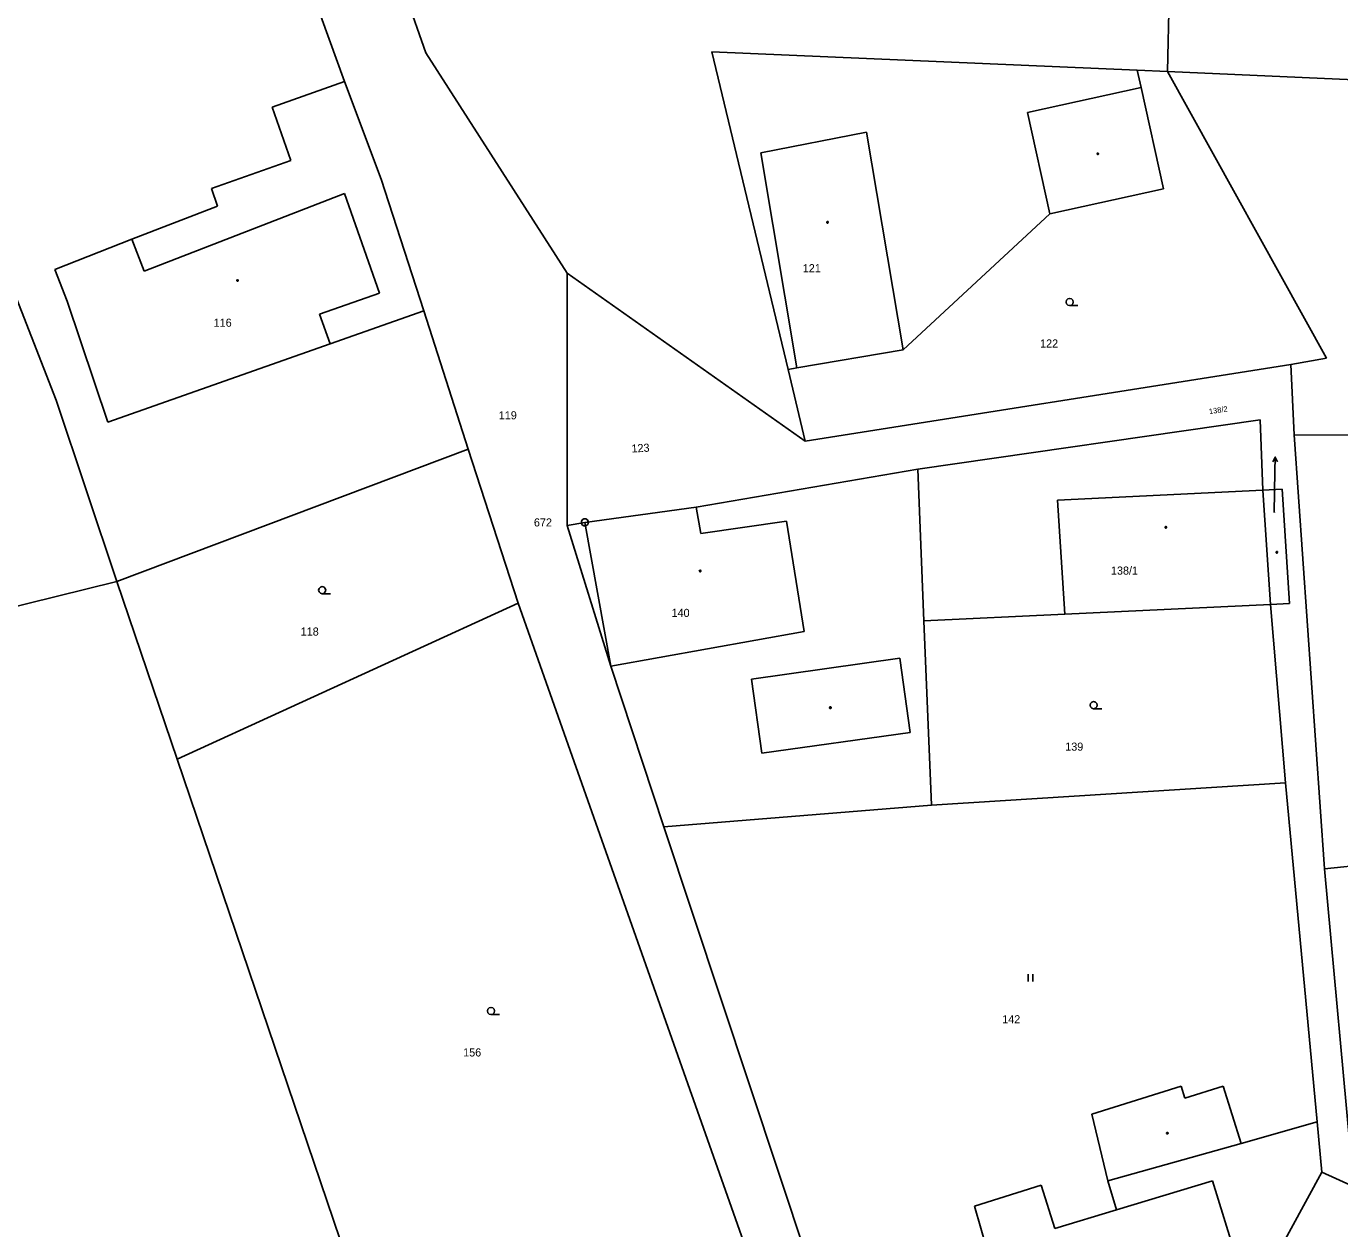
# Model space of a CAD drawing. Extents: x -871430 to -870620, y -1010094 to -1009649.
# Drawn here: x -870823.3 to -870754.3, y -1009884.4 to -1009821.3 of the extents above; entities that cross this region are included whole.
import ezdxf

# ---------------------------------------------------------------- set-up
doc = ezdxf.new("R2010")
doc.units = 0
for name, color, linetype in [('Vrstva 1', 7, 'Continuous'), ('Vrstva 2', 7, 'Continuous'), ('Vrstva 3', 7, 'Continuous'), ('Vrstva 4', 7, 'Continuous'), ('Vrstva 5', 7, 'Continuous'), ('Vrstva 7', 7, 'Continuous'), ('Vrstva 8', 7, 'Continuous')]:
    doc.layers.add(name, color=color, linetype=linetype)

msp = doc.modelspace()

# ---------------------------------------------------------------- linework, layer by layer
at = {"layer": 'Vrstva 1'}
for p, q in [((-870762.97, -1009806.25), (-870763.36, -1009823.67)), ((-870806.27, -1009811.26), (-870802.3, -1009822.69)), ((-870806.57, -1009824.19), (-870810.92, -1009812.17)), ((-870821.71, -1009840.91), (-870830.96, -1009817.26)), ((-870802.3, -1009822.69), (-870794.88, -1009834.25)), ((-870764.95, -1009823.6), (-870787.29, -1009822.63)), ((-870787.29, -1009822.63), (-870783.28, -1009839.3)), ((-870763.36, -1009823.67), (-870764.95, -1009823.6)), ((-870764.95, -1009823.6), (-870764.75, -1009824.51)), ((-870755.01, -1009838.71), (-870763.36, -1009823.67)), ((-870744.58, -1009824.51), (-870763.36, -1009823.67)), ((-870810.37, -1009825.53), (-870806.57, -1009824.19)), ((-870804.65, -1009829.31), (-870806.57, -1009824.19)), ((-870764.75, -1009824.51), (-870763.58, -1009829.82)), ((-870810.37, -1009825.53), (-870809.38, -1009828.34)), ((-870813.56, -1009829.81), (-870809.38, -1009828.34)), ((-870802.41, -1009836.23), (-870804.65, -1009829.31)), ((-870813.56, -1009829.81), (-870813.24, -1009830.73)), ((-870769.54, -1009831.14), (-870763.58, -1009829.82)), ((-870813.24, -1009830.73), (-870817.74, -1009832.47)), ((-870769.54, -1009831.14), (-870777.24, -1009838.28)), ((-870817.74, -1009832.47), (-870821.78, -1009834.05)), ((-870821.78, -1009834.05), (-870821.13, -1009835.72)), ((-870794.88, -1009834.25), (-870794.88, -1009847.5)), ((-870794.88, -1009834.25), (-870782.38, -1009843.06)), ((-870821.13, -1009835.72), (-870818.99, -1009842.07)), ((-870807.33, -1009837.96), (-870802.41, -1009836.23)), ((-870800.07, -1009843.48), (-870802.41, -1009836.23)), ((-870818.99, -1009842.07), (-870807.33, -1009837.96)), ((-870782.82, -1009839.22), (-870777.24, -1009838.28)), ((-870756.88, -1009839.04), (-870755.01, -1009838.71)), ((-870783.28, -1009839.3), (-870782.82, -1009839.22)), ((-870783.28, -1009839.3), (-870782.38, -1009843.06)), ((-870782.38, -1009843.06), (-870756.88, -1009839.04)), ((-870756.88, -1009839.04), (-870756.72, -1009842.74)), ((-870818.53, -1009850.43), (-870821.71, -1009840.91)), ((-870776.47, -1009844.53), (-870758.5, -1009841.94)), ((-870758.5, -1009841.94), (-870758.35, -1009845.64)), ((-870756.72, -1009842.74), (-870755.12, -1009865.52)), ((-870746.99, -1009842.77), (-870756.72, -1009842.74)), ((-870818.53, -1009850.43), (-870800.07, -1009843.48)), ((-870800.07, -1009843.48), (-870797.46, -1009851.56)), ((-870788.1, -1009846.53), (-870776.47, -1009844.53)), ((-870776.47, -1009844.53), (-870776.15, -1009852.5)), ((-870757.35, -1009845.59), (-870758.35, -1009845.64)), ((-870758.35, -1009845.64), (-870757.96, -1009851.63)), ((-870757.35, -1009845.59), (-870756.96, -1009851.58)), ((-870793.95, -1009847.33), (-870788.1, -1009846.53)), ((-870794.88, -1009847.5), (-870793.95, -1009847.33)), ((-870794.88, -1009847.5), (-870792.59, -1009854.88)), ((-870838.76, -1009855.45), (-870818.53, -1009850.43)), ((-870815.36, -1009859.75), (-870818.53, -1009850.43)), ((-870797.46, -1009851.56), (-870815.36, -1009859.75)), ((-870784.39, -1009888.53), (-870797.46, -1009851.56)), ((-870757.96, -1009851.63), (-870768.75, -1009852.15)), ((-870756.96, -1009851.58), (-870757.96, -1009851.63)), ((-870757.96, -1009851.63), (-870757.17, -1009861)), ((-870768.75, -1009852.15), (-870776.15, -1009852.5)), ((-870776.15, -1009852.5), (-870775.76, -1009862.17)), ((-870792.59, -1009854.88), (-870789.8, -1009863.3)), ((-870803.69, -1009894.13), (-870815.36, -1009859.75)), ((-870775.76, -1009862.17), (-870757.17, -1009861)), ((-870757.17, -1009861), (-870755.51, -1009878.79)), ((-870775.76, -1009862.17), (-870789.8, -1009863.3)), ((-870789.8, -1009863.3), (-870779.56, -1009894.18)), ((-870738.92, -1009863.81), (-870755.12, -1009865.52)), ((-870755.12, -1009865.52), (-870753.63, -1009881.72)), ((-870762.65, -1009876.91), (-870767.34, -1009878.38)), ((-870762.65, -1009876.91), (-870762.45, -1009877.54)), ((-870762.45, -1009877.54), (-870760.44, -1009876.91)), ((-870759.5, -1009879.92), (-870760.44, -1009876.91)), ((-870766.5, -1009881.89), (-870767.34, -1009878.38)), ((-870755.51, -1009878.79), (-870759.5, -1009879.92)), ((-870755.51, -1009878.79), (-870755.26, -1009881.44)), ((-870759.65, -1009889.46), (-870755.26, -1009881.44)), ((-870755.26, -1009881.44), (-870753.59, -1009882.19)), ((-870769.99, -1009882.12), (-870773.49, -1009883.22)), ((-870769.28, -1009884.39), (-870769.99, -1009882.12)), ((-870766.5, -1009881.89), (-870766.04, -1009883.41)), ((-870773.49, -1009883.22), (-870772.83, -1009885.52)), ((-870766.04, -1009883.41), (-870769.28, -1009884.39))]:
    msp.add_line(p, q, dxfattribs=at)
at = {"layer": 'Vrstva 3'}
for p, q in [((-870770.685, -1009871.045), (-870770.685, -1009871.42)), ((-870770.435, -1009871.42), (-870770.435, -1009871.045))]:
    msp.add_line(p, q, dxfattribs=at)
for points in [[(-870768.5, -1009835.95), (-870768.595, -1009835.925), (-870768.662, -1009835.855), (-870768.688, -1009835.762), (-870768.662, -1009835.67), (-870768.595, -1009835.6), (-870768.5, -1009835.575), (-870768.405, -1009835.6), (-870768.338, -1009835.67), (-870768.312, -1009835.762), (-870768.338, -1009835.855), (-870768.405, -1009835.925), (-870768.5, -1009835.95), (-870768.062, -1009835.95)], [(-870807.74, -1009851.07), (-870807.835, -1009851.045), (-870807.902, -1009850.975), (-870807.928, -1009850.882), (-870807.902, -1009850.79), (-870807.835, -1009850.72), (-870807.74, -1009850.695), (-870807.645, -1009850.72), (-870807.578, -1009850.79), (-870807.552, -1009850.882), (-870807.578, -1009850.975), (-870807.645, -1009851.045), (-870807.74, -1009851.07), (-870807.302, -1009851.07)], [(-870767.24, -1009857.11), (-870767.335, -1009857.085), (-870767.402, -1009857.015), (-870767.428, -1009856.922), (-870767.402, -1009856.83), (-870767.335, -1009856.76), (-870767.24, -1009856.735), (-870767.145, -1009856.76), (-870767.078, -1009856.83), (-870767.052, -1009856.922), (-870767.078, -1009857.015), (-870767.145, -1009857.085), (-870767.24, -1009857.11), (-870766.802, -1009857.11)], [(-870798.88, -1009873.16), (-870798.975, -1009873.135), (-870799.042, -1009873.065), (-870799.068, -1009872.972), (-870799.042, -1009872.88), (-870798.975, -1009872.81), (-870798.88, -1009872.785), (-870798.785, -1009872.81), (-870798.718, -1009872.88), (-870798.692, -1009872.972), (-870798.718, -1009873.065), (-870798.785, -1009873.135), (-870798.88, -1009873.16), (-870798.442, -1009873.16)]]:
    msp.add_lwpolyline(points, dxfattribs=at)
at = {"layer": 'Vrstva 4'}
for p, q in [((-870770.71, -1009825.82), (-870764.75, -1009824.51)), ((-870770.71, -1009825.82), (-870769.54, -1009831.14)), ((-870784.72, -1009827.94), (-870779.17, -1009826.84)), ((-870779.17, -1009826.84), (-870777.24, -1009838.28)), ((-870782.82, -1009839.22), (-870784.72, -1009827.94)), ((-870817.09, -1009834.15), (-870806.57, -1009830.06)), ((-870806.57, -1009830.06), (-870804.73, -1009835.29)), ((-870817.74, -1009832.47), (-870817.09, -1009834.15)), ((-870807.88, -1009836.4), (-870804.73, -1009835.29)), ((-870807.33, -1009837.96), (-870807.88, -1009836.4)), ((-870758.35, -1009845.64), (-870769.14, -1009846.16)), ((-870788.1, -1009846.53), (-870787.86, -1009847.91)), ((-870768.75, -1009852.15), (-870769.14, -1009846.16)), ((-870787.86, -1009847.91), (-870783.37, -1009847.26)), ((-870783.37, -1009847.26), (-870782.43, -1009853.05)), ((-870792.59, -1009854.88), (-870793.95, -1009847.33)), ((-870782.43, -1009853.05), (-870792.59, -1009854.88)), ((-870785.2, -1009855.55), (-870777.41, -1009854.46)), ((-870776.87, -1009858.35), (-870777.41, -1009854.46)), ((-870784.66, -1009859.44), (-870785.2, -1009855.55)), ((-870776.87, -1009858.35), (-870784.66, -1009859.44)), ((-870766.5, -1009881.89), (-870759.5, -1009879.92)), ((-870761, -1009881.88), (-870766.04, -1009883.41)), ((-870761, -1009881.88), (-870759.12, -1009887.92))]:
    msp.add_line(p, q, dxfattribs=at)
at = {"layer": 'Vrstva 5'}
for points in [[(-870766.998, -1009827.942), (-870766.975, -1009827.98), (-870766.998, -1009828.018), (-870767.042, -1009828.018), (-870767.065, -1009827.98), (-870767.042, -1009827.942), (-870766.998, -1009827.942)], [(-870781.21, -1009831.538), (-870781.185, -1009831.542), (-870781.172, -1009831.565), (-870781.168, -1009831.58), (-870781.172, -1009831.602), (-870781.192, -1009831.62), (-870781.21, -1009831.622), (-870781.232, -1009831.615), (-870781.247, -1009831.6), (-870781.252, -1009831.58), (-870781.247, -1009831.558), (-870781.227, -1009831.54), (-870781.21, -1009831.538)], [(-870812.19, -1009834.588), (-870812.165, -1009834.592), (-870812.152, -1009834.615), (-870812.148, -1009834.63), (-870812.152, -1009834.652), (-870812.172, -1009834.67), (-870812.19, -1009834.672), (-870812.212, -1009834.665), (-870812.227, -1009834.65), (-870812.232, -1009834.63), (-870812.227, -1009834.608), (-870812.207, -1009834.59), (-870812.19, -1009834.588)], [(-870763.45, -1009847.548), (-870763.425, -1009847.552), (-870763.412, -1009847.575), (-870763.408, -1009847.59), (-870763.412, -1009847.612), (-870763.432, -1009847.63), (-870763.45, -1009847.632), (-870763.472, -1009847.625), (-870763.487, -1009847.61), (-870763.492, -1009847.59), (-870763.487, -1009847.568), (-870763.467, -1009847.55), (-870763.45, -1009847.548)], [(-870757.62, -1009848.858), (-870757.595, -1009848.862), (-870757.582, -1009848.885), (-870757.578, -1009848.9), (-870757.582, -1009848.922), (-870757.602, -1009848.94), (-870757.62, -1009848.942), (-870757.642, -1009848.935), (-870757.658, -1009848.92), (-870757.662, -1009848.9), (-870757.658, -1009848.878), (-870757.638, -1009848.86), (-870757.62, -1009848.858)], [(-870787.9, -1009849.838), (-870787.875, -1009849.842), (-870787.862, -1009849.865), (-870787.858, -1009849.88), (-870787.862, -1009849.902), (-870787.883, -1009849.92), (-870787.9, -1009849.922), (-870787.922, -1009849.915), (-870787.938, -1009849.9), (-870787.942, -1009849.88), (-870787.938, -1009849.858), (-870787.918, -1009849.84), (-870787.9, -1009849.838)], [(-870781.038, -1009857.013), (-870781.015, -1009857.05), (-870781.038, -1009857.088), (-870781.082, -1009857.088), (-870781.105, -1009857.05), (-870781.082, -1009857.013), (-870781.038, -1009857.013)], [(-870763.348, -1009879.352), (-870763.325, -1009879.39), (-870763.348, -1009879.428), (-870763.392, -1009879.428), (-870763.415, -1009879.39), (-870763.392, -1009879.352), (-870763.348, -1009879.352)]]:
    msp.add_lwpolyline(points, dxfattribs=at)
at = {"layer": 'Vrstva 7'}
for p in [(-870757.707, -1009843.9), (-870757.76, -1009846.81)]:
    msp.add_line(p, (-870757.72, -1009844.65), dxfattribs=at)
msp.add_lwpolyline([(-870757.836, -1009844.148), (-870757.707, -1009843.9), (-870757.586, -1009844.152)], dxfattribs=at)
at = {"layer": 'Vrstva 8'}
msp.add_line((-870793.962, -1009847.33), (-870793.938, -1009847.33), dxfattribs=at)
msp.add_lwpolyline([(-870793.902, -1009847.15), (-870793.818, -1009847.198), (-870793.77, -1009847.282), (-870793.77, -1009847.38), (-870793.818, -1009847.465), (-870793.902, -1009847.512), (-870794, -1009847.512), (-870794.085, -1009847.465), (-870794.132, -1009847.38), (-870794.132, -1009847.282), (-870794.085, -1009847.198), (-870794, -1009847.15), (-870793.902, -1009847.15)], dxfattribs=at)

# ---------------------------------------------------------------- texts
at = {"layer": 'Vrstva 2'}
for s, height, p in [('121', 0.425, (-870782.512, -1009834.2)), ('116', 0.425, (-870813.442, -1009837.06)), ('122', 0.425, (-870770.052, -1009838.15)), ('119', 0.425, (-870798.472, -1009841.92)), ('138/2', 0.025, (-870757.754, -1009846.81)), ('138/1', 0.425, (-870766.332, -1009850.07)), ('140', 0.425, (-870789.402, -1009852.29)), ('118', 0.425, (-870808.872, -1009853.27)), ('139', 0.425, (-870768.732, -1009859.31)), ('142', 0.425, (-870772.042, -1009873.62)), ('156', 0.425, (-870800.342, -1009875.36))]:
    msp.add_text(s, height=height, dxfattribs=at).set_placement(p)
msp.add_text('123', height=0.425, rotation=3.03668, dxfattribs=at).set_placement((-870791.492, -1009843.665))
at = {"layer": 'Vrstva 7'}
msp.add_text('138/2', height=0.285, rotation=8.47978, dxfattribs=at).set_placement((-870761.165, -1009841.65))
at = {"layer": 'Vrstva 8'}
msp.add_text('672', height=0.425, dxfattribs=at).set_placement((-870796.627, -1009847.542))

doc.saveas('drawing.dxf')
